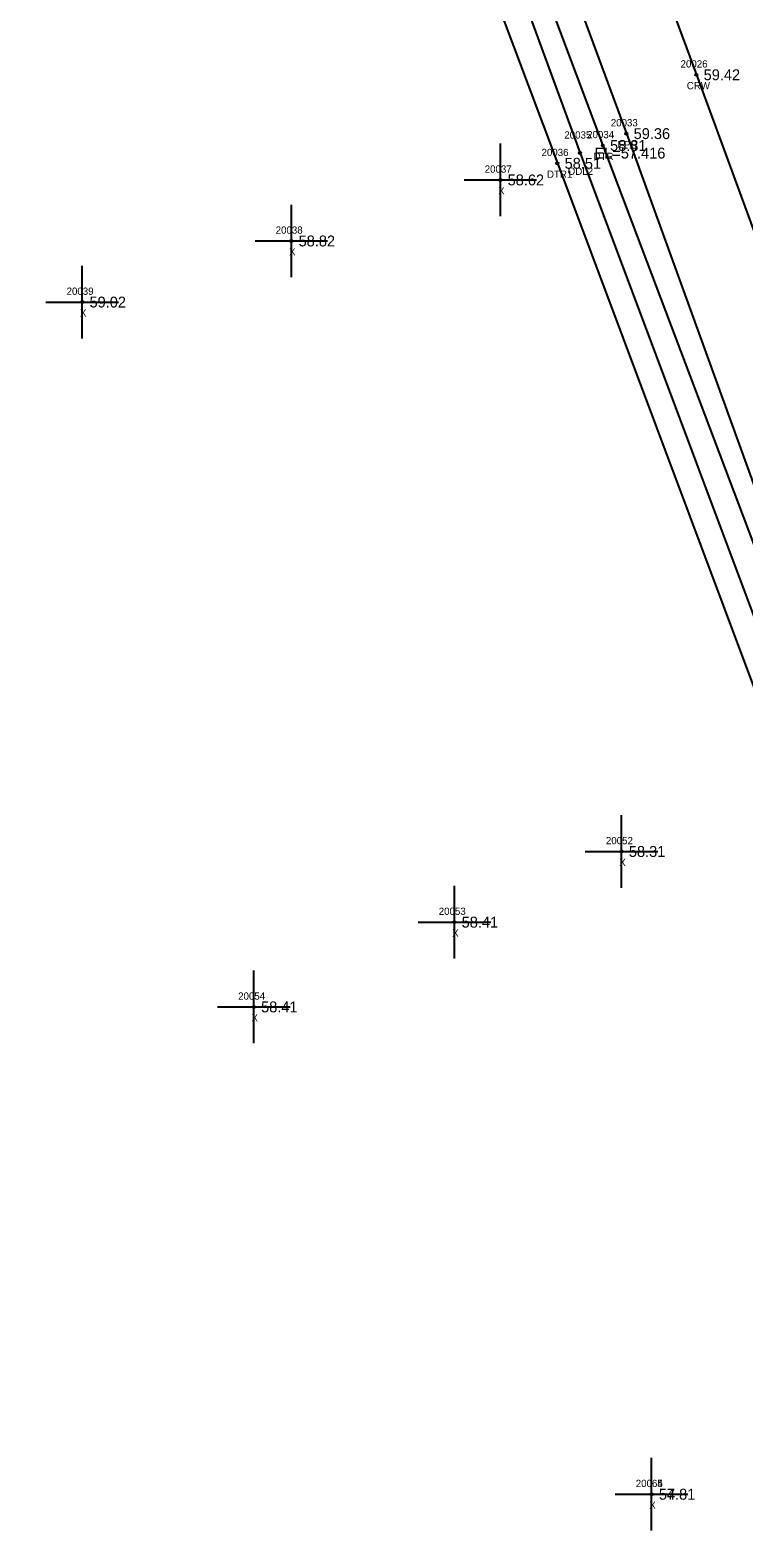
# Model space of a CAD drawing. Extents: x 2396547 to 2397655, y 770185 to 772649.
# Drawn here: x 2396647.5 to 2396745.8, y 772225.3 to 772433 of the extents above; entities that cross this region are included whole.
import ezdxf

# ---------------------------------------------------------------- set-up
doc = ezdxf.new("R2010")
doc.units = 0
for name, color, linetype in [('RD_DTM_BkLn1', 7, 'Continuous'), ('RD_EX_H2O', 7, 'Continuous'), ('RD_EX_H2O_txCode', 7, 'Continuous'), ('RD_EX_Misc', 7, 'Continuous'), ('RD_EX_Misc_txCode', 7, 'Continuous'), ('RD_EX_Road', 7, 'Continuous'), ('RD_EX_Road_txCode', 7, 'Continuous'), ('RD_EX_TX_H2O_ELEV', 7, 'Continuous'), ('RD_EX_TX_Misc_ELEV', 7, 'Continuous'), ('RD_EX_TX_Road_ELEV', 7, 'Continuous'), ('RD_HC_Survey_ELEV', 7, 'Continuous'), ('RD_HC_Survey_txCode', 7, 'Continuous'), ('RD_SMD_Locator', 7, 'Continuous')]:
    doc.layers.add(name, color=color, linetype=linetype)

msp = doc.modelspace()

# ---------------------------------------------------------------- linework, layer by layer
at = {"layer": 'RD_DTM_BkLn1'}
msp.add_lwpolyline([(2396669.86, 772614.94), (2396704.28, 772521.49), (2396739.29, 772426.89), (2396775.36, 772328.69), (2396800.21, 772259.35), (2396825.58, 772185.8), (2396852.46, 772104.52), (2396872.48, 772041.55), (2396897.57, 771959.72), (2396918.76, 771888.68), (2396939.09, 771818.34), (2396959.29, 771747.62), (2396993.72, 771617.68), (2397022.56, 771506.67), (2397049.1, 771404.69)], dxfattribs=at)
at = {"layer": 'RD_EX_H2O'}
for points in [[(2396652.28, 772609.21), (2396687.19, 772514.46), (2396723.26, 772416.1), (2396755.2, 772330.94), (2396781.71, 772252.52)], [(2396654.89, 772610.44), (2396689.53, 772515.4), (2396726.4, 772417.15), (2396758.49, 772332.26), (2396786.59, 772254.26)], [(2396647.52, 772607.47), (2396683.51, 772512.21), (2396720.14, 772414.69), (2396752.02, 772329.6), (2396778.94, 772251.31)]]:
    msp.add_lwpolyline(points, dxfattribs=at)
at = {"layer": 'RD_EX_Misc'}
for p, q in [((2396712.29, 772407.4), (2396712.29, 772417.4)), ((2396707.29, 772412.4), (2396717.29, 772412.4)), ((2396683.5, 772398.99), (2396683.5, 772408.99)), ((2396678.5, 772403.99), (2396688.5, 772403.99)), ((2396654.7, 772390.57), (2396654.7, 772400.57)), ((2396649.7, 772395.57), (2396659.7, 772395.57)), ((2396728.99, 772314.87), (2396728.99, 772324.87)), ((2396723.99, 772319.87), (2396733.99, 772319.87)), ((2396705.96, 772305.13), (2396705.96, 772315.13)), ((2396700.96, 772310.13), (2396710.96, 772310.13)), ((2396678.33, 772293.45), (2396678.33, 772303.45)), ((2396673.33, 772298.45), (2396683.33, 772298.45)), ((2396733.12, 772226.3), (2396733.12, 772236.3)), ((2396733.12, 772226.3), (2396733.12, 772236.3)), ((2396728.12, 772231.3), (2396738.12, 772231.3)), ((2396728.12, 772231.3), (2396738.12, 772231.3))]:
    msp.add_line(p, q, dxfattribs=at)
at = {"layer": 'RD_EX_Road'}
msp.add_lwpolyline([(2396658.78, 772611.07), (2396693.37, 772516.9), (2396729.65, 772418.78), (2396760.7, 772333.11), (2396788.58, 772254.87), (2396814.65, 772181.57), (2396841.1, 772100.86), (2396861.19, 772037.76), (2396886.09, 771955.71), (2396907.15, 771884.49), (2396928.56, 771811.72), (2396947.65, 771744.09), (2396985.17, 771602.64), (2397011.11, 771504.04), (2397037.95, 771404.25), (2397039, 771401.22)], dxfattribs=at)
at = {"layer": 'RD_SMD_Locator'}
for centre in [(2396739.29, 772426.89), (2396729.65, 772418.78), (2396723.26, 772416.1), (2396726.4, 772417.15), (2396720.14, 772414.69), (2396712.29, 772412.4), (2396683.5, 772403.99), (2396654.7, 772395.57), (2396728.99, 772319.87), (2396705.96, 772310.13), (2396678.33, 772298.45), (2396733.12, 772231.3), (2396733.12, 772231.3)]:
    msp.add_circle(centre, 0.15, dxfattribs=at)

# ---------------------------------------------------------------- texts
at = {"layer": 'RD_EX_H2O_txCode'}
for s, p in [('20035', (2396721.1, 772418.1)), ('20034', (2396724.24, 772418.15)), ('20036', (2396717.96, 772415.69)), ('DTR', (2396725.13, 772415.15)), ('DTR1', (2396718.71, 772412.69)), ('ODL2', (2396721.57, 772413.1))]:
    msp.add_text(s, height=1, dxfattribs=at).set_placement(p)
at = {"layer": 'RD_EX_Misc_txCode'}
for s, p in [('20037', (2396710.13, 772413.4)), ('X', (2396711.98, 772410.4)), ('20038', (2396681.34, 772404.99)), ('X', (2396683.18, 772401.99)), ('20039', (2396652.54, 772396.57)), ('X', (2396654.38, 772393.57)), ('20052', (2396726.83, 772320.87)), ('X', (2396728.67, 772317.87)), ('20053', (2396703.8, 772311.13)), ('X', (2396705.65, 772308.13)), ('20054', (2396676.17, 772299.45)), ('X', (2396678.01, 772296.45)), ('20064', (2396730.94, 772232.3)), ('20065', (2396730.94, 772232.3)), ('X', (2396732.8, 772229.3)), ('X', (2396732.8, 772229.3))]:
    msp.add_text(s, height=1, dxfattribs=at).set_placement(p)
at = {"layer": 'RD_EX_Road_txCode'}
for s, p in [('20033', (2396727.5, 772419.78)), ('EPR', (2396728.42, 772416.78))]:
    msp.add_text(s, height=1, dxfattribs=at).set_placement(p)
at = {"layer": 'RD_EX_TX_H2O_ELEV'}
for s, p in [('58.81', (2396727.4, 772416.4)), ('EL=57.416', (2396725.26, 772415.35)), ('58.51', (2396721.14, 772413.94))]:
    msp.add_text(s, height=1.5, dxfattribs=at).set_placement(p)
at = {"layer": 'RD_EX_TX_Misc_ELEV'}
for s, p in [('58.62', (2396713.29, 772411.65)), ('58.82', (2396684.5, 772403.24)), ('59.02', (2396655.7, 772394.82)), ('58.31', (2396729.99, 772319.12)), ('58.41', (2396706.96, 772309.38)), ('58.41', (2396679.33, 772297.7)), ('57.81', (2396734.12, 772230.55)), ('54.81', (2396734.12, 772230.55))]:
    msp.add_text(s, height=1.5, dxfattribs=at).set_placement(p)
at = {"layer": 'RD_EX_TX_Road_ELEV'}
msp.add_text('59.36', height=1.5, dxfattribs=at).set_placement((2396730.65, 772418.03))
at = {"layer": 'RD_HC_Survey_ELEV'}
msp.add_text('59.42', height=1.5, dxfattribs=at).set_placement((2396740.29, 772426.14))
at = {"layer": 'RD_HC_Survey_txCode'}
for s, p in [('20026', (2396737.11, 772427.89)), ('CRW', (2396737.97, 772424.89))]:
    msp.add_text(s, height=1, dxfattribs=at).set_placement(p)

doc.saveas('drawing.dxf')
